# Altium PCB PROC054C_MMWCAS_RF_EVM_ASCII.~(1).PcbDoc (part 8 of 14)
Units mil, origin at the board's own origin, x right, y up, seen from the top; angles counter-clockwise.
Board outline 6299.21 x 5370.07 mil, 8 copper layers (L1 TOP, L2 GND, L3 SIGNAL 1, L4 GND, L5 SIGNAL 2, L6 SIGNAL 3, L7 GND, L8 BOTTOM), stack 53.5 mil thick; 775 components, 552 nets, 2648 pads, 7845 vias.
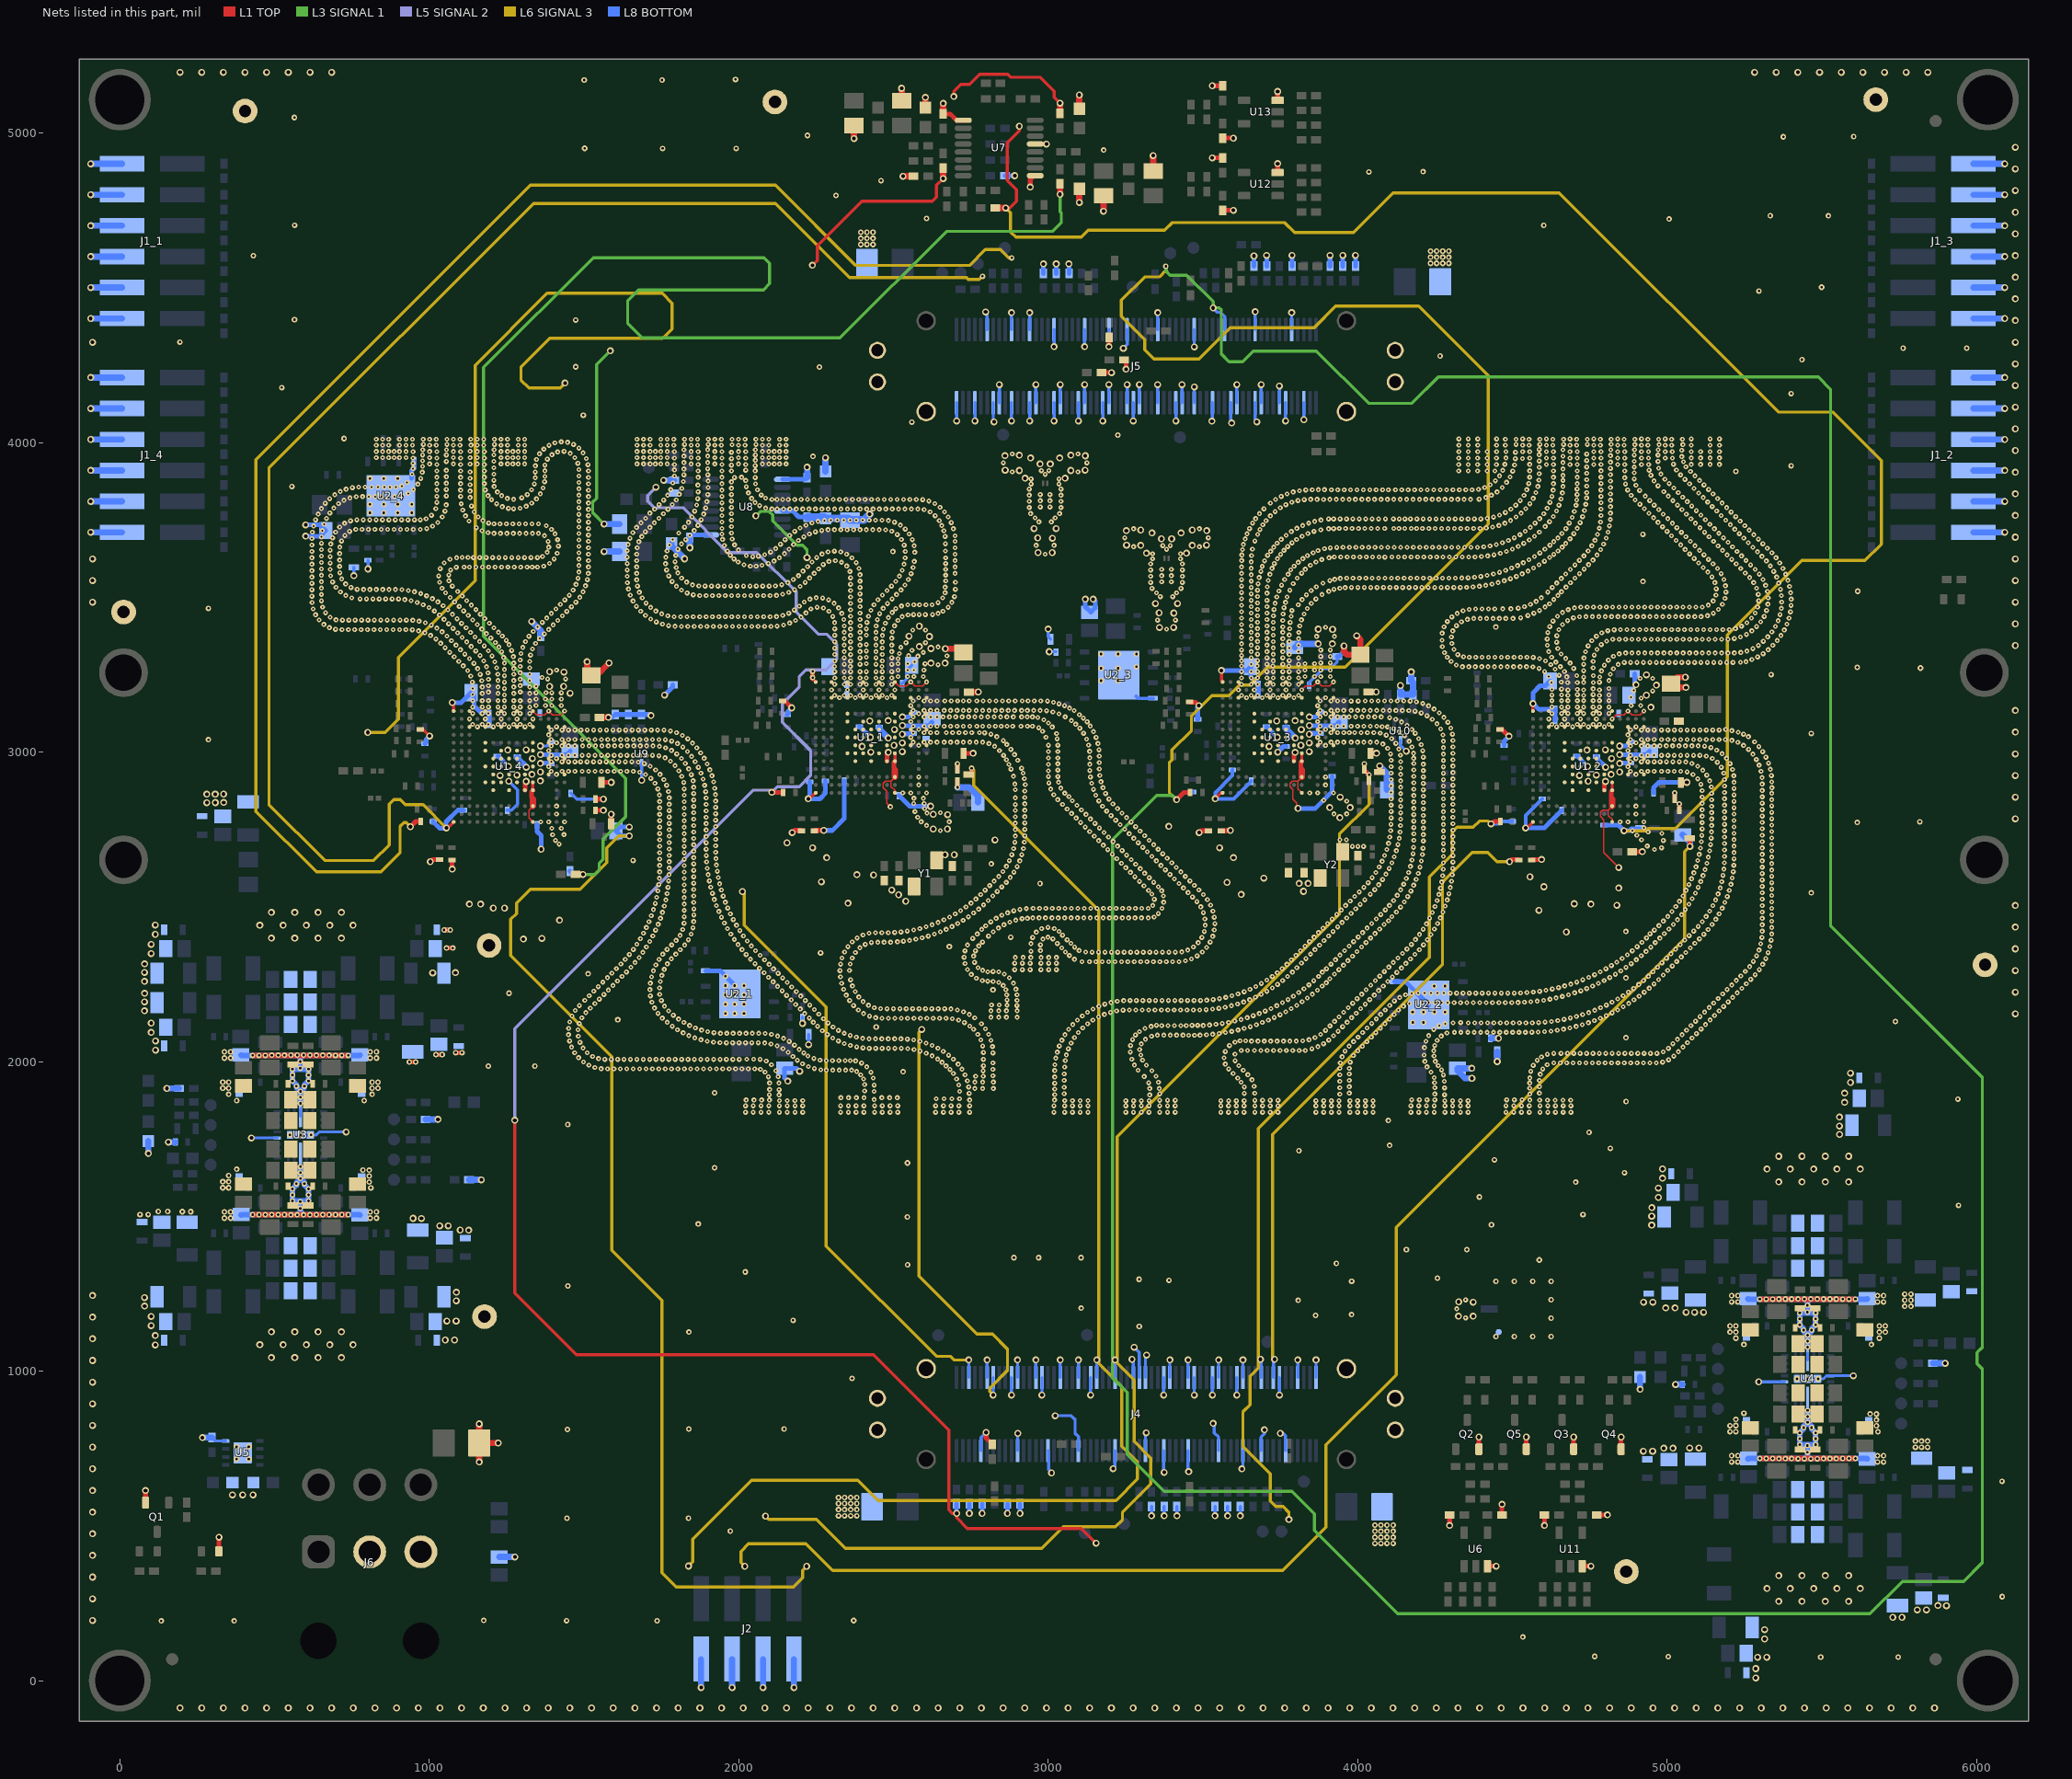
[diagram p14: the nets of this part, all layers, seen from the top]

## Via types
v1: diameter 13.77/15.74 (per signal layer), hole 5.9, L1 TOP to L2 GND, tented both sides, 5522 vias
v2: diameter 22.4, hole 12.2, L1 TOP to L8 BOTTOM, tented both sides, 1522 vias
v3: diameter 18, hole 8, L1 TOP to L8 BOTTOM, tented both sides, 727 vias
v4: diameter 18, hole 7.87, L1 TOP to L8 BOTTOM, tented top, 50 vias
v5: diameter 24, hole 12, L1 TOP to L8 BOTTOM, tented both sides, 13 vias
v6: diameter 19.68, hole 7.87, L1 TOP to L8 BOTTOM, tented top, 10 vias
v7: diameter 13.77/15.74 (per signal layer), hole 5.9, L1 TOP to L2 GND, tented top, 1 vias

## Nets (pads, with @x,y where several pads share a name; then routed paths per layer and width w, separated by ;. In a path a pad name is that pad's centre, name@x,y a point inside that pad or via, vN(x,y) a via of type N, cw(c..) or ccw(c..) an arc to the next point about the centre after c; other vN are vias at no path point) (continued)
GND: (continued)
  other v1: 4349.11,1172.28 4320.23,1201.17 4349.11,1230.06 2021.98,1836.34 2046.98,1836.34 2071.98,1836.34 2096.98,1836.34 2131.75,1836.34 2156.75,1836.34 2181.75,1836.34 2206.75,1836.34 2329.18,1836.34 2354.18,1836.34 2379.18,1836.34 2404.18,1836.34 2438.95,1836.34 2463.95,1836.34 2488.95,1836.34 2513.95,1836.34 2636.38,1836.34 2661.38,1836.34 2686.38,1836.34 2711.38,1836.34 2746.15,1836.34 3018.58,1836.34 3053.35,1836.34 3078.35,1836.34 3103.35,1836.34 3128.35,1836.34 3250.78,1836.34 3275.78,1836.34 3300.78,1836.34 3325.78,1836.34 3360.55,1836.34 3385.55,1836.34 3410.55,1836.34 3557.98,1836.34 3582.98,1836.34 3607.98,1836.34 3632.98,1836.34 3667.75,1836.34 3692.75,1836.34 3717.75,1836.34 3742.75,1836.34 3865.18,1836.34 3890.18,1836.34 3915.18,1836.34 3940.18,1836.34 3974.95,1836.34 3999.95,1836.34 4024.95,1836.34 4049.95,1836.34 4172.38,1836.34 4197.38,1836.34 4222.38,1836.34 4247.38,1836.34 4282.15,1836.34 4307.15,1836.34 4332.15,1836.34 4357.15,1836.34 4479.58,1836.34 4504.58,1836.34 4529.58,1836.34 4554.58,1836.34 4589.35,1836.34 4614.35,1836.34 4639.35,1836.34 4664.35,1836.34 4689.35,1836.34 2021.98,1857.01 2046.98,1857.01 2071.98,1857.01 2096.98,1857.01 2131.75,1857.01 2156.75,1857.01 2181.75,1857.01 2206.75,1857.01 2329.18,1857.01 2354.18,1857.01 2379.18,1857.01 2404.18,1857.01 2438.95,1857.01 2463.95,1857.01 2488.95,1857.01 2513.95,1857.01 2636.38,1857.01 2661.38,1857.01 2686.38,1857.01 2711.38,1857.01 2746.15,1857.01 3018.58,1857.01 3053.35,1857.01 3078.35,1857.01 3103.35,1857.01 3128.35,1857.01 3250.78,1857.01 3275.78,1857.01 3300.78,1857.01 3325.78,1857.01 3360.55,1857.01 3385.55,1857.01 3410.55,1857.01 3557.98,1857.01 3582.98,1857.01 3607.98,1857.01 3632.98,1857.01 3667.75,1857.01 3692.75,1857.01 3717.75,1857.01 3742.75,1857.01 3865.18,1857.01 3890.18,1857.01 3915.18,1857.01 3940.18,1857.01 3974.95,1857.01 3999.95,1857.01 4024.95,1857.01 4049.95,1857.01 4172.38,1857.01 4197.38,1857.01 4222.38,1857.01 4247.38,1857.01 4282.15,1857.01 4307.15,1857.01 4332.15,1857.01 4357.15,1857.01 4479.58,1857.01 4504.58,1857.01 4529.58,1857.01 4554.58,1857.01 4589.35,1857.01 4614.35,1857.01 4639.35,1857.01 4664.35,1857.01 4689.35,1857.01 2131.52,1874.05 2156.52,1874.05 2181.52,1874.05 2206.52,1874.05 3053.52,1874.05 3078.52,1874.05 3103.52,1874.05 3128.52,1874.05 3251.02,1873.55 3276.02,1873.55 3301.02,1873.55 3326.02,1873.55 3558.22,1873.55 3583.22,1873.55 3608.22,1873.55 3633.22,1873.55 3865.18,1873.55 3890.18,1873.55 3915.18,1873.55 3940.18,1873.55 3974.95,1873.55 3999.95,1873.55 4024.95,1873.55 4049.95,1873.55 4282.02,1873.55 4307.02,1873.55 4332.02,1873.55 4357.02,1873.55 3360.52,1875.05 3385.52,1875.05 3410.52,1875.05 3667.72,1875.05 3692.72,1875.05 3717.72,1875.05 3742.72,1875.05 4588.44,1875.48 4613.44,1875.48 4638.44,1875.48 4663.44,1875.48 4688.44,1875.48 2024.07,1875.88 2049.07,1875.88 2074.07,1875.88 2099.07,1875.88 2746,1876 3020.66,1875.94 4174.47,1876.36 4199.47,1876.36 4224.47,1876.36 4249.47,1876.36 4481.67,1876.48 4506.67,1876.48 4531.67,1876.48 4556.66,1876.12 2437.5,1877.63 2638.47,1879.93 2663.47,1879.93 2688.47,1879.93 2713.47,1879.94 2330.03,1883.3 2355.03,1883.3 2380.03,1883.3 2405.03,1883.3 2462.42,1883.3 2487.42,1883.3 2512.42,1883.3 2130.38,1892.3 3328.18,1892.34 2099,1893 3021.06,1893.43 4281,1893 3942.42,1895.05 4249.54,1895.11 4556.66,1895.14 3051.74,1896.3 3360.52,1895.72 2744.62,1897.27 3633.86,1897.29 3667.55,1897.85 3973.1,1898.3 4587.34,1898.3 2437.42,1903.97 2713.76,1903.82 2406.82,1905.33 2130.38,1908.97 2099.7,1910.17 3021.06,1911.1 2763.18,1913.14 2788.18,1913.14 2822.95,1913.14 3328.18,1913.01 3359.02,1913.17 4556,1914 4281,1915 3942.42,1915.72 4249.54,1915.78 3051.74,1916.97 2743.14,1917.89 3633.86,1917.96 3973.1,1918.97 4587.34,1918.97 3665.36,1920.35 2437.5,1923.97 2710.7,1924.26 2406.82,1926 3021.06,1929.77 2099.7,1930.84 2130.22,1931 3324.93,1931.36 4556,1931 4248.7,1932 2763.18,1933.81 2788.18,1933.81 2822.95,1933.81 3356.38,1933.67 3623.45,1933.7 3942.42,1936.39 4280.21,1936.44 2738.73,1938.08 3051.74,1939.64 3973.1,1939.64 4587.34,1939.64 3658.45,1941.4 2403.49,1943.7 2703.99,1943.81 2434.75,1946.58 3612.39,1946.91 4556.66,1947.48 4247.84,1948.23 3021.06,1950.44 2095.61,1950.94 2127.65,1951.51 3310.43,1951.87 2765.27,1952.87 2790.26,1952.68 3348.62,1952.83 2821.4,1954.43 2394.01,1957 2731.49,1957.44 3942.42,1957.06 4277.26,1956.9 3645.16,1957.52 4590.1,1959.41 3051.74,1960.31 3973.1,1960.31 2693.86,1961.83 3597.78,1961.52 2085,1966 2426.93,1965.71 4237.29,1966 2381,1968 4559.53,1968.76 2790,1970 3335.32,1970.36 2120.1,1970.75 3021.06,1971.11 3290.7,1971.97 3630.54,1972.14 2283.31,1972.59 2303.98,1972.59 2324.65,1972.59 2345.32,1972.59 2364.91,1972.59 4271.1,1973.15 2264.98,1973.68 2683.06,1974.35 2070,1975 2821.4,1975.1 2721.56,1975.57 3583.16,1976.14 4598.1,1976.05 1555.56,1977.19 1576.22,1976.72 1596.89,1976.72 1617.56,1976.72 1638.23,1976.72 1658.9,1976.72 1679.57,1976.72 1700.24,1976.72 1720.91,1976.72 1741.58,1976.72 1762.25,1976.72 1782.92,1976.72 1803.59,1976.72 1824.26,1976.72 1844.93,1976.72 1865.6,1976.72 1886.27,1976.72 1906.94,1976.72 1927.61,1976.72 1948.28,1976.72 1968.95,1976.72 1989.62,1976.72 2010.29,1976.72 2030.96,1976.72 2051.63,1976.72 2244.66,1977.48 3942.42,1977.73 3973.09,1977.72 1535.23,1980.91 3053.15,1982.35 2413.58,1983.1 4224.21,1982.8 2225.03,1983.96 2670.01,1986 2790.72,1986.61 3615.93,1986.75 4260.61,1987 1515.9,1988.23 3317.5,1988.18 4567.54,1987.81 3278.75,1988.83 2105.84,1989.84 3021.31,1989.95 4612.4,1989.95 2709.14,1992.09 3572.52,1991.76 2206.44,1992.98 2396.94,1995.36 2821.4,1995.77 3944.04,1995.88 4633.62,1995.66 4655.2,1995.66 4675.87,1995.66 4696.54,1995.66 4717.21,1995.66 4737.88,1995.66 4758.55,1995.66 4779.22,1995.66 4799.89,1995.66 4820.56,1995.66 4841.23,1995.66 4861.9,1995.66 4882.57,1995.66 4903.24,1995.66 4923.91,1995.66 4944.58,1995.66 4965.25,1995.67 2657.01,1998 3976.07,1998.17 4985.74,1998.41 1498.2,1998.91 4217.26,2000.65 4251.01,2001 2088.93,2001.72 2377.41,2002.12 2283.31,2003.26 2302.9,2003.27 2323.57,2003.27 2344.24,2003.27 2360.55,2003.27 3055.2,2003.15 3604.35,2002.75 2189.21,2004.4 4580.15,2004.19 2262.71,2004.98 3305.03,2004.67 5005.02,2005.86 1567.44,2007.4 1588.11,2007.4 1608.78,2007.4 1629.45,2007.4 1650.12,2007.4 1670.79,2007.4 1691.46,2007.4 1712.13,2007.4 1732.8,2007.4 1753.47,2007.4 1774.14,2007.4 1794.81,2007.4 1815.48,2007.4 1836.15,2007.4 1856.82,2007.4 1877.49,2007.4 1898.16,2007.4 1918.83,2007.4 1939.5,2007.4 1960.17,2007.4 1980.84,2007.4 2001.51,2007.4 2068.98,2007.15 2693.86,2007.49 2790.72,2007.28 2026,2008 2048,2008 2642.67,2008.19 3270.29,2007.69 1546.88,2009.59 2242.68,2010.08 3024.3,2011.41 3568.31,2012 1482.71,2012.6 4594.2,2015.25 2175.26,2016.4 3949.75,2015.75 1527.49,2016.73 2223.77,2018.43 2624.74,2018.47 4247.01,2018 5022.04,2017.6 3986.68,2019.68 2678.03,2020.79 3299.35,2021.16 4214.86,2021.05 3058.74,2021.71 3603.7,2023.85 4613.14,2023.51 4633.62,2026.34 4657.22,2026.34 4677.89,2026.34 4698.56,2026.34 4719.23,2026.34 4739.9,2026.34 4760.57,2026.34 4781.24,2026.34 4801.91,2026.34 4822.58,2026.34 4843.25,2026.34 4863.92,2026.34 4884.59,2026.34 4905.26,2026.34 4925.93,2026.34 4946.6,2026.34 4967.27,2026.44 2605.93,2027.04 1510.43,2028.42 2210,2028 2821.43,2027.98 1469.84,2028.77 2159.84,2030.18 2790.74,2029.66 3029.35,2030.52 3265.27,2031.1 4987.35,2031.35 5036.78,2032.09 2661.18,2032.75 3572.32,2032.65 2586.41,2033.83 3959.32,2034 4000.63,2034.94 4246.04,2034.83 3623.76,2035.72 3644.43,2035.72 3666.45,2035.72 3687.12,2035.72 3707.79,2035.72 3728.46,2035.72 3749.13,2035.72 3769.8,2035.72 3790.47,2035.72 3811.14,2035.73 3831,2036 2566.34,2038.79 3295.52,2038.86 2195.52,2039.52 3065.38,2041.29 3852,2041.37 2142.65,2041.64 2545.9,2041.86 2421.91,2043.07 2442.58,2043.03 2463.25,2043.03 2483.92,2043.03 2504.59,2043.03 2525.26,2043.02 2643.41,2043.31 5004.38,2043.07 1496.68,2043.85 2401.28,2044.32 4215.96,2045.32 1459.92,2046.91 2380.83,2047.33 5051.39,2046.7 3871.5,2048.24 2819.88,2048.59 2788.43,2050.2 3035.89,2050.12 3972.35,2050.04 4015.24,2049.55 2124,2050.57 2360.71,2052.06 2624.83,2052.37 3266.05,2051.76 3585.84,2051.78 4249.01,2052 2180.09,2053.28 2104.28,2056.76 3300.84,2057.21 2341.07,2058.49 3889.9,2057.65 5018.99,2057.68 2083.88,2060.11 2605.58,2059.9 3074.14,2060.01 1939.21,2061.03 1959.87,2060.72 1980.54,2060.72 2001.21,2060.72 2021.88,2060.72 2042.55,2060.72 2063.22,2060.72 5066.01,2061.32 1486.84,2062.02 1918.6,2062.72 3603.44,2062.62 4029.86,2064.17 2163.16,2065.14 3986.97,2064.66 4220.58,2065.47 1453.24,2066.47 1898.18,2065.88 2585.78,2065.83 3657.1,2066.4 3677.77,2066.4 3698.44,2066.4 3719.11,2066.4 3739.78,2066.4 3760.45,2066.4 3781.12,2066.4 3801.79,2066.4 2322.04,2066.57 3620,2067 3638,2067 3822.45,2066.97 2815.28,2068.74 3044.26,2069.02 3906.88,2069.44 4257,2068.71 2565.56,2070.12 2782.24,2069.92 1878.03,2070.5 3272.88,2071.27 3842.79,2070.66 3314.58,2072.33 5033.61,2072.3 2545.06,2072.75 2421.06,2073.77 2441.73,2073.71 2462.4,2073.71 2483.07,2073.71 2503.74,2073.71 2524.41,2073.71 2144.96,2074.93 2400.44,2075.29 2303.77,2076.25 5080.62,2075.93 1858.27,2076.55 3084.89,2077.66 3862.23,2077.69 2380.08,2078.81 4001.59,2079.28 4044.47,2078.78 1481.39,2081.96 3334.01,2082 2125.74,2082.54 3922.15,2083.36 4270.25,2082.71 1838.98,2084 2360.15,2084.29 4229.56,2084.08 3353.04,2085.35 3373.71,2085.35 3394.38,2085.35 3415.05,2085.35 3435.72,2085.35 3454.01,2085 3473,2085 3282.01,2086 3490.7,2085.69 1449.99,2086.88 2286.4,2087.44 3054.37,2087.05 3511.34,2086.72 5048.23,2086.92 2105.76,2087.84 2772.38,2088.09 2807.72,2087.98 3531.94,2088.43 3880.22,2087.86 1961.29,2091.4 1981.96,2091.4 2002.63,2091.4 2023.3,2091.4 2043.97,2091.4 2064.64,2091.4 2085.3,2090.77 3552.47,2090.83 5095.24,2090.55 1940.62,2091.67 2340.85,2091.7 4288.66,2092.25 1820.29,2092.81 1920.03,2093.45 4059.09,2093.4 3097.52,2094.03 3572.91,2093.91 4016.2,2093.89 4313.03,2094.66 4333.7,2094.66 4356.32,2094.66 4376.99,2094.66 4397.66,2094.66 4418.33,2094.66 4439,2094.66 4459.67,2094.66 4480.34,2094.66 4501.01,2094.66 4521.68,2094.66 4542.35,2094.66 4563.02,2094.7 4583.68,2095.29 1899.64,2096.88 3295.16,2096.61 4604.31,2096.61 3593.24,2097.66 3936.77,2097.98 4624.88,2098.64 2270.04,2100.07 2322.36,2100.94 3896.27,2100.89 4645.36,2101.38 1879.6,2101.92 3613.43,2102.08 5062.84,2101.53 1480.64,2102.62 1802.27,2102.94 2759.24,2104.04 3066.14,2104.04 4246.18,2103.76 4665.74,2104.84 5109.86,2105.17 2797.38,2105.88 3312.89,2107.23 3633.46,2107.18 1450.28,2107.55 4073.71,2108.02 1860.02,2108.56 3111.86,2108.91 4030.82,2108.51 4685.99,2109 2304.87,2111.95 3653.31,2112.93 3951.39,2112.6 1785.02,2114.33 2254.81,2114.05 3332.49,2113.8 4706.08,2113.86 2746.95,2114.8 3910.89,2115.49 3366.68,2116.03 3387.35,2116.03 3408.02,2116.03 3428.69,2116.03 3446,2116 4263.19,2115.51 5077.46,2116.15 1841.04,2116.74 3350.01,2117 3465.01,2117 3483,2117 3500.92,2116.84 3521.54,2118.27 3672.96,2119.34 4725.99,2119.42 3079.47,2119.84 3542.1,2120.43 5124.47,2119.78 2784.49,2122.04 3127.61,2122.3 1484.61,2122.9 3562.57,2123.31 4045.43,2123.12 4088.32,2122.63 4282.51,2122.85 2288.53,2124.61 4308.2,2125.34 4357.74,2125.34 4378.41,2125.34 4399.08,2125.34 4419.75,2125.34 4440.42,2125.34 4461.09,2125.34 4481.76,2125.34 4502.43,2125.34 4523.1,2125.34 4543.77,2125.34 4564.44,2125.4 1822.78,2126.42 2729.53,2125.93 3692.39,2126.4 4333,2126 4585.1,2126.08 4745.69,2125.67 1768.63,2126.93 2241,2127 3582.93,2126.89 3966,2127.21 1454.09,2127.86 4605.72,2127.52 3925.51,2130.11 4626.27,2129.71 3603.14,2131.19 5092.07,2130.76 4646.73,2132.65 4765.16,2132.6 2710.5,2134 3094.2,2134.34 3144.58,2134.1 3711.57,2134.1 5139.09,2134.4 3623.2,2136.18 4667.07,2136.35 4102.94,2137.25 1805.35,2137.53 4060.05,2137.74 2273.47,2138.77 2690.39,2138.77 2463.06,2140.14 2483.73,2140.14 2504.4,2140.14 2525.07,2140.14 2545.74,2140.14 2566.41,2140.14 2587.08,2140.14 2607.75,2140.14 2628.42,2140.14 2649.09,2140.14 2669.76,2140.14 4784.38,2140.21 1753.19,2140.67 2227.99,2140.87 2762.5,2141.46 4687.26,2140.78 1493.11,2141.74 2442.46,2141.83 3643.07,2141.88 3730.49,2142.43 3980.62,2141.83 2814.98,2143.54 2839.98,2143.54 2864.98,2143.54 2899.75,2143.54 3162.61,2144.21 3940.13,2144.73 5106.69,2145.38 4707.27,2145.96 1461.3,2147.23 2422.45,2146.98 3110.11,2147.53 3662.73,2148.26 4803.33,2148.48 5153.7,2149.01 1788.87,2150.01 3749.12,2151.39 2744.99,2152.46 4074.66,2152.35 4117.55,2151.86 4727.08,2151.86 2258.85,2153.39 3181.53,2152.54 2213.37,2155.49 2403.58,2155.44 3682.15,2155.33 1739.12,2155.81 3995.23,2156.44 4821.97,2157.4 1505.68,2158.15 4746.66,2158.49 3127.08,2159.33 3201.16,2159 3954.74,2159.34 5121.31,2160 2726.17,2161 3767.44,2160.96 3701.32,2163.07 1773.44,2163.76 2814.98,2164.21 2839.98,2164.21 2864.98,2164.21 2899.75,2164.21 3221.33,2163.53 5168.32,2163.63 1471.72,2165.09 3241.84,2166.1 4132.17,2166.48 4765.98,2165.83 2386.42,2166.96 2706.38,2166.95 3262.5,2166.72 3283.17,2166.72 3303.84,2166.72 3324.51,2166.72 3345.18,2166.72 3365.85,2166.72 3386.52,2166.72 3407.19,2166.72 3427.86,2166.72 3448.53,2166.72 3469.2,2166.72 3489.87,2166.79 4089.28,2166.97 4840.3,2166.96 2244.24,2168 3510.52,2167.62 3531.12,2169.41 2198.76,2170.1 2685.96,2170.19 3144.99,2169.66 2458.6,2170.91 2479.27,2170.82 2499.94,2170.82 2520.61,2170.82 2541.28,2170.82 2561.95,2170.82 2582.62,2170.82 2603.29,2170.82 2623.96,2170.82 2644.63,2170.82 2665.3,2170.82 3720.2,2171.48 3785.44,2171.13 4009.85,2171.06 3551.6,2172.15 1520.29,2172.78 1727.75,2173.07 2438.19,2174.18 3969.36,2173.96 4785.02,2173.87 5135.92,2174.61 3571.94,2175.83 4858.28,2177.16 3163.7,2178.44 5182.94,2178.25 1759.85,2179.34 4148.56,2179.08 3592.09,2180.45 1485.03,2180.9 2371.41,2181.17 2899,2181 3738.78,2180.54 2419.04,2181.95 2867.06,2182.35 3803.08,2181.89 4103.9,2181.59 2229.62,2182.62 2817.07,2183.08 2842.07,2183.08 4803.75,2182.61 2184.14,2184.72 3183.09,2185.61 3612,2186 4024.46,2185.68 1534.9,2187.39 4167.52,2187.3 4875.89,2187.97 3983.97,2188.57 5150.54,2189.23 3757.03,2190.24 3203.01,2191.11 4187.92,2190.65 4208.59,2190.72 4229.26,2190.72 4249.93,2190.72 4270.6,2190.72 4291.27,2190.72 4311.94,2190.72 4332.61,2190.72 4353.28,2190.72 4373.95,2190.72 4394.62,2190.72 4415.29,2190.72 4435.96,2190.72 4456.63,2190.72 4477.3,2190.72 4497.97,2190.72 4518.63,2190.9 1719.48,2192.01 3631.63,2192.47 4539.29,2191.72 4822.15,2192.03 3820.36,2193.24 4559.9,2193.21 5197.55,2192.86 2402.13,2193.84 3223.33,2194.91 4580.46,2195.36 4118.94,2195.76 2215.01,2197.23 2358.42,2197.25 3243.9,2196.99 3264.56,2197.4 3285.23,2197.4 3305.9,2197.4 3326.57,2197.4 3347.24,2197.4 3367.91,2197.4 3388.58,2197.4 3409.25,2197.4 3429.92,2197.4 3450.59,2197.4 3471.26,2197.4 1502.33,2198.2 1750.1,2197.56 2899.01,2198 3491.93,2197.51 4600.94,2198.18 2169.53,2199.33 2867,2199 3512.58,2198.51 4893.12,2199.39 3650.95,2199.83 4039.08,2200.29 3533.15,2200.53 3774.94,2200.57 1549.52,2202.01 4621.31,2201.66 4840.2,2202.11 3998.59,2203.19 3553.59,2203.57 5165.15,2203.84 3837.26,2205.15 4641.57,2205.8 4136.1,2207.28 5212.17,2207.48 3573.86,2207.62 3669.9,2208.08 2388.01,2208.93 4661.67,2210.59 4909.94,2211.41 1714.54,2212.09 2200.39,2211.85 3792.47,2211.52 1516.94,2212.81 3593.9,2212.68 4857.86,2212.86 2154.91,2213.95 2347.49,2214.79 4053.69,2214.91 2866,2216 2899.01,2216 4155.05,2215.54 4681.62,2216.02 1564.14,2216.62 3688.45,2217.21 1744.74,2217.53 3853.74,2217.61 4013.21,2217.81 5179.77,2218.46 3613.67,2218.73 4175.17,2220.27 4195.81,2221.4 4216.48,2221.4 4237.15,2221.4 4257.82,2221.4 4278.49,2221.4 4299.16,2221.4 4319.83,2221.4 4340.5,2221.4 4361.17,2221.4 4381.84,2221.4 4402.51,2221.4 4423.18,2221.4 4443.85,2221.4 4464.52,2221.4 4485.19,2221.4 4505.86,2221.4 4526.53,2221.83 4701.37,2222.1 5226.78,2222.09 3809.6,2223.08 4547.17,2222.96 4875.11,2224.24 4926.33,2224 4567.76,2224.79 2185.77,2226.47 2376.36,2226.01 3633.11,2225.75 1531.56,2227.43 3706.55,2227.17 4588.27,2227.32 2140.29,2228.57 4720.92,2228.82 4068.31,2229.53 1578.75,2231.24 3869.81,2230.61 4608.69,2230.55 2863,2232 4027.82,2232.42 1713.09,2232.7 5194.39,2233.08 2338.8,2233.55 2895.57,2234.14 3652.18,2233.72 4628.98,2234.46 3826.33,2235.23 4740.24,2236.16 4891.93,2236.25 4942.28,2237.15 5241.4,2236.71 1743.92,2238.18 3724.18,2237.97 4649.13,2239.07 2171.16,2241.08 1546.18,2242.04 2125.68,2243.18 3670.83,2242.64 3885.44,2244.15 4082.93,2244.14 4669.12,2244.35 4759.31,2244.13 2367.4,2244.63 1593.37,2245.85 2854.56,2246.1 4042.44,2247.04 3842.61,2247.96 5209,2247.69 4908.31,2248.86 3741.29,2249.57 4688.91,2250.32 4957.75,2250.86 5256.02,2251.33 3689.01,2252.47 1714.46,2253.33 2332.48,2253.22 2887.81,2253.3 4778.12,2252.71 3899,2255 2156.54,2255.7 2840.01,2256 1560.79,2256.66 4708.49,2256.95 2111.06,2257.8 1746.3,2258.71 2822,2259 4097.54,2258.76 1607.99,2260.47 2804.33,2259.66 3858.45,2261.24 2787.32,2261.62 3757.84,2261.95 4057.05,2261.65 4796.64,2261.89 4924.21,2262.07 5223.62,2262.31 3706.68,2263.19 2361.34,2264.4 4727.83,2264.24 4972.75,2265.09 5270.63,2265.94 3910.37,2267.74 2768.04,2269.07 2141.93,2270.31 1575.41,2271.27 2874.56,2270.74 2096.45,2272.41 4746.91,2272.19 4814.85,2271.67 4112.16,2273.37 1718.14,2273.67 2328.62,2273.53 1622.6,2275.08 3723.8,2274.78 3773.8,2275.09 3873.81,2275.07 4071.67,2276.27 4939.61,2275.85 5238.23,2276.92 1751.43,2278.74 4987.38,2279.69 4765.71,2280.77 5284.96,2280.84 2751.54,2281.52 3924.99,2282.36 4832.74,2282.03 2857.86,2282.92 2127.31,2284.93 1590.03,2285.89 2081.83,2287.03 3740.32,2287.2 4126.77,2287.99 3789.14,2288.94 3886,2289 1637.22,2289.7 2804.33,2290.34 2840,2290 4784.21,2290 4954.5,2290.19 2822,2291 4086.29,2290.89 5252.85,2291.54 1724.08,2293.47 4850.28,2292.96 2327.28,2294.16 5001.99,2294.3 2357.96,2294.69 2788.45,2295.1 2891.78,2297.14 2916.78,2297.14 2941.78,2297.14 2976.55,2297.14 3001.55,2297.14 3026.55,2297.14 3939.6,2296.97 5297.88,2296.97 1759.21,2297.89 2739.11,2297.67 2112.69,2299.55 3756.2,2300.43 3899.32,2300.07 4802.38,2299.84 1604.64,2300.5 2067.22,2301.64 2773.23,2303.22 3803.87,2303.44 4141.39,2302.61 4867.46,2304.46 1651.48,2304.66 4100.9,2305.5 4969.12,2304.81 5266.77,2306.81 5016.61,2308.92 4820.21,2310.3 1732.2,2312.47 3954.22,2311.59 2098.08,2314.16 3771.41,2314.43 5309.17,2314.29 1619.23,2315.15 2328.87,2314.77 2360.16,2315.24 3913.94,2314.69 1769.5,2315.81 2052.6,2316.26 2731.15,2316.74 4156,2317.22 4884.25,2316.5 2891.78,2317.81 2916.78,2317.81 2941.78,2317.81 2976.55,2317.81 3001.55,2317.81 3026.55,2317.81 3818.49,2318.06 4983.73,2319.42 1665.08,2320.22 4115.52,2320.12 2762.08,2320.62 4837.67,2321.36 3109,2323 3133.47,2322.66 3154.14,2322.66 3174.81,2322.66 3195.48,2322.66 3216.15,2322.66 3236.82,2322.66 3257.49,2322.66 3278.16,2322.66 3298.83,2322.66 3319.5,2322.66 3340.17,2322.66 3360.84,2322.66 3381.51,2322.66 3402.18,2322.66 3422.85,2322.83 5031.22,2323.53 5278.89,2323.56 3443.32,2325.67 3968.83,2326.2 2083.46,2328.78 3786.06,2329.01 3928.56,2329.31 4900.65,2329.08 1633.29,2330.3 1742.42,2330.44 2038.04,2330.94 3085.17,2330.57 1782.12,2332.19 3463.02,2331.92 4170.62,2331.84 3833.1,2332.67 4854.75,2333 5318.74,2332.61 4998.35,2334.04 2333.76,2334.85 2366.67,2334.86 4130.13,2334.73 1677.99,2336.37 2728.4,2337.23 2893.87,2336.68 2918.87,2336.68 2943.87,2336.68 2976.72,2336.68 3001.72,2336.68 3026.72,2336.68 5045.84,2338.15 2759.22,2341.1 3481.39,2341.4 3983.45,2340.82 4916.64,2342.19 5289.03,2341.57 2068.85,2343.39 3068.53,2342.83 3800.68,2343.63 3943.17,2343.92 4871.42,2345.22 1646.63,2346.09 2024,2346.1 4185.23,2346.46 1754.58,2347.15 1796.53,2347.01 3847.72,2347.29 4144.75,2349.35 5012.96,2348.65 5326.48,2351.78 1690.18,2353.06 2377.2,2352.65 3142.09,2353.34 3162.76,2353.34 3183.43,2353.34 3204.1,2353.34 3224.77,2353.34 3245.44,2353.34 3266.11,2353.34 3286.78,2353.34 3307.45,2353.34 3328.12,2353.34 3348.79,2353.34 3369.46,2353.34 3390.13,2353.34 3410.8,2353.34 5060.46,2352.77 2341.84,2353.88 3055.55,2354.15 3121,2354 3497.89,2353.85 3431.43,2354.59 3998.07,2355.44 2944.28,2356.3 4932.19,2355.8 2054.45,2358.22 2731.07,2357.73 2765,2358 3815.29,2358.24 4887.67,2358 2974.96,2359.02 3100,2359 3957.79,2358.54 3451.31,2360.27 5297.07,2360.62 1659.22,2362.49 1768.54,2362.4 1811.14,2361.62 2010.58,2361.82 3862.33,2361.91 4199.38,2361.53 5027.58,2363.27 4159.37,2363.97 3044.17,2367.2 5075.07,2367.38 2391.3,2367.76 3512.06,2368.9 1701.63,2370.27 3085.75,2369.85 3469.39,2370.27 4012.68,2370.05 4947.29,2369.92 2352.88,2371.35 4903.48,2371.32 5332.33,2371.6 3829.91,2372.86 3972.4,2373.15 2040.68,2373.64 2776,2374 1783.16,2377.02 1825.37,2376.62 2738.96,2376.83 2975.03,2377.04 3876.95,2376.52 4212.78,2377.27 1997.8,2378.07 5042.2,2377.89 1671.02,2379.45 2408.78,2378.79 4173.69,2378.86 5302.9,2380.45 2944.49,2381.09 3029.55,2381.81 3073.5,2382.1 5089.69,2382 3484.77,2384.08 4961.98,2384.46 2428.56,2384.79 4027.3,2384.67 4918.82,2385.17 2449.21,2385.77 2469.88,2385.77 2490.55,2385.77 2787.85,2386.16 3523.49,2386.13 2366.6,2386.8 2513,2387 3844.52,2387.48 1712.31,2387.97 3987.02,2387.77 2532,2389 2027.6,2389.64 3891.56,2391.14 1797.74,2391.66 2552.05,2391.74 5336.22,2391.9 5056.81,2392.5 1837.22,2393.55 3060.99,2393.75 4187.23,2394.48 4225.41,2393.63 1985.69,2394.82 2572.38,2395.48 2982.82,2396.19 3014.94,2396.43 1682.03,2396.95 5104.3,2396.61 2756.27,2397.96 4041.91,2399.28 4976.59,2399.08 2382.88,2399.54 2592.53,2400.11 4933.68,2399.54 2949.58,2401.13 3496.66,2400.99 5306.44,2400.81 2999.15,2401.95 3859.14,2402.09 4001.63,2402.38 2807.19,2405.5 3531.84,2405.03 1722.22,2406.11 2015.21,2406.19 2612.44,2405.63 3906.18,2405.75 5071.43,2407.12 1810.22,2408.14 3046.38,2408.37 2401.3,2408.93 4199.94,2410.78 4237.23,2410.59 5118.83,2411.32 1846.16,2412.19 1974.27,2412.05 2632.1,2412.03 5338.13,2412.48 2770.88,2412.57 4945,2413 4056.53,2413.9 4991.21,2413.7 1692.2,2414.94 2421.16,2414.64 2441.75,2416.45 2462.42,2416.45 2483.09,2416.48 2503.75,2417.23 3873.75,2416.71 4016.25,2417 2961.64,2418.38 2524.35,2418.96 2651.46,2419.28 2822.53,2419.35 3504.44,2420.14 3920.8,2420.37 3035.15,2420.95 5307.66,2421.45 2544.84,2421.66 5086.04,2421.73 2003.54,2423.25 1731.32,2424.67 2565.19,2425.32 3536.89,2425.08 4958.89,2424.76 1818.87,2426.91 2670.47,2427.38 2785.5,2427.19 5132.61,2426.73 4211.78,2427.72 4248.21,2428.1 5005.82,2428.31 4071.14,2428.51 1963.55,2429.72 2585.33,2429.94 2978.9,2429.76 3019.45,2429.62 3888.37,2431.32 1851.95,2432.03 2839.21,2431.56 4030.87,2431.62 1701.52,2433.39 5338.34,2433.15 2999.19,2433.7 2605.24,2435.5 3935.41,2434.99 2689.11,2436.32 5100.43,2436.57 2798.19,2438.97 4973.51,2439.37 1992.62,2440.8 3507.72,2440.55 2624.86,2442 2857.05,2442 5307.66,2442.12 4085.76,2443.13 5020.17,2443.19 5145.47,2442.91 1739.6,2443.61 4222.72,2445.26 2707.34,2446.07 3538.49,2445.68 3902.99,2445.94 4045.48,2446.23 4258.34,2446.12 1823.3,2447.1 1953.55,2447.81 2644.15,2449.42 3950.03,2449.6 2875.87,2450.56 1709.97,2452.25 2814.43,2451.75 5113.9,2452.25 1854.44,2452.55 4988.11,2454 5338.34,2453.82 4100,2455 2725.12,2456.61 2895.46,2457.15 2663.07,2457.75 1982.45,2458.8 5033.85,2458.69 5157.37,2459.81 3506.59,2461.19 3917.6,2460.56 4060.1,2460.85 2915.62,2461.71 1747.05,2462.89 2831.75,2463.04 2933,2463 4232.74,2463.34 5307.66,2462.79 3964.64,2464.22 2950.01,2464.66 2970.68,2464.66 2991.35,2464.66 3012.02,2464.66 3032.69,2464.66 3053.36,2464.66 3074.03,2464.66 3094.7,2464.66 3115.37,2464.66 3136.04,2464.66 3156.71,2464.66 3177.38,2464.66 3198.05,2464.66 3218.72,2464.66 3239.39,2464.66 3260.06,2464.66 3280.73,2464.66 3301.4,2464.66 3323.28,2464.66 4267.58,2464.61 1944.29,2466.29 3536.84,2466.29 2681.58,2466.96 3342,2467 1823.86,2467.77 2742.41,2467.93 4111.02,2468.39 5002.25,2469.08 5126.34,2468.76 1717.54,2471.49 2850,2472.74 1855,2474 5338.34,2474.49 3932.22,2475.17 4074.71,2475.46 5046.83,2474.77 1973.07,2477.22 2699.63,2477.03 5168.26,2477.38 3355.84,2478.15 3979.26,2478.83 2759.19,2480 2869.03,2480.79 3501.61,2481.25 1753.65,2482.48 4241.79,2481.93 4125.19,2483.44 5307.66,2483.46 4275.92,2483.52 1935.79,2485.13 5015.66,2484.81 3532.19,2486.43 5137.7,2486.03 2888.71,2487.12 1823.86,2488.44 2717.18,2487.94 3946.83,2489.79 4089.33,2490.08 1724.19,2491.06 5059.09,2491.42 2908.87,2491.67 1855,2493 2775.42,2492.8 3993.87,2493.45 2929.36,2494.42 2951.22,2495.34 2971.89,2495.34 2992.56,2495.34 3013.23,2495.34 3033.9,2495.34 3054.57,2495.34 3075.24,2495.34 3095.91,2495.34 3116.58,2495.34 3137.25,2495.34 3157.92,2495.34 3178.59,2495.34 3199.26,2495.34 3219.93,2495.34 3240.6,2495.34 3261.27,2495.34 3281.94,2495.34 3302.61,2495.34 3323.28,2495.34 3367.78,2495.02 5338.34,2495.16 1964.49,2496.02 5178.12,2495.55 4138.44,2499.3 2734.2,2499.67 3492.97,2500.03 4249.87,2500.95 5028.31,2501.16 1759.39,2502.33 4283.33,2502.82 1928.05,2504.3 3337.93,2504.44 3961.45,2504.41 5147.94,2503.98 5307.66,2504.13 4103.02,2504.66 2791.07,2506.31 3524.65,2505.67 4008.49,2508.07 1823.86,2509.11 5070.6,2508.58 1729.93,2510.92 2750.64,2512.2 5186.9,2514.26 1854.54,2514.56 1956.73,2515.18 3373.44,2514.9 4150.72,2515.93 5338.34,2515.83 3480.98,2516.86 5040.17,2518.08 3976.06,2519.02 2806.1,2520.49 4256.94,2520.38 4116.16,2520.62 1764.25,2522.42 4289.8,2522.45 4023.1,2522.68 5157.03,2522.55 1921.08,2523.76 3342.98,2524.48 3514.37,2523.61 2766.48,2525.48 5307.66,2524.8 5081.34,2526.24 1823.86,2529.78 1734.73,2531.02 3466.57,2531.68 4161.98,2533.26 5194.58,2533.45 3990.68,2533.64 1854.54,2535.23 1949.79,2534.65 2820.73,2535.1 3372.17,2535.53 5051.22,2535.55 4128.23,2537.4 5338.34,2536.5 2781.67,2539.5 3501.58,2539.85 4262.99,2540.14 3335,2541 4041.07,2540.65 4295.31,2542.37 5164.91,2541.66 1768.24,2542.7 1914.92,2543.49 5091.3,2544.36 5307.66,2545.47 3451.95,2546.3 4005.29,2548.25 1823.86,2550.45 2835.34,2549.71 1738.58,2551.33 4172.18,2551.24 3367,2552 3324.13,2553.19 5201.13,2553.05 1943.7,2554.4 2796.33,2554.08 5061.44,2553.52 3487.07,2554.56 4139.17,2554.93 1854.54,2555.9 4055.23,2555.71 5338.34,2557.17 4268,2560.19 3437.33,2560.92 5171.56,2561.23 1771.33,2563.14 1909.55,2563.45 4019.91,2562.87 4299.85,2562.54 5100.44,2562.9 2849.96,2564.33 3355.84,2564.86 5307.66,2566.14 3309.51,2567.81 2810.94,2568.69 3472.45,2569.18 4181.3,2569.79 1823.86,2571.12 1741.49,2571.8 4068.43,2571.62 5070.79,2571.95 4148.94,2573.15 5206.54,2573 1938.46,2574.39 3422.72,2575.53 1854.54,2576.57 4033.98,2578.01 5338.34,2577.84 2864.39,2579.13 3341.23,2579.48 4271.96,2580.48 5176.95,2581.18 3294.9,2582.43 5108.75,2581.82 2825.56,2583.31 4303.41,2582.9 1773.53,2583.69 1904.99,2583.61 3457.84,2583.79 5307.66,2586.81 4080.62,2588.31 4189.28,2588.86 3408.1,2590.15 5079.26,2590.81 1743.44,2592.37 1823.86,2591.79 4157.49,2591.97 5210.77,2593.23 3326.61,2594.09 4046.99,2594.07 1934.08,2594.6 2877.6,2595.03 1854.54,2597.24 3280.28,2597.04 2840.08,2598.01 3443.22,2598.41 5338.34,2598.51 4274.86,2600.95 5116.23,2601.09 5181.06,2601.44 4305.98,2603.41 1774.83,2604.32 1901.25,2603.94 3393.49,2604.76 4091.76,2605.72 5307.66,2607.48 4196.12,2608.37 3312,2608.71 5086.83,2610.04 4058.88,2610.98 4164.79,2611.31 1823.86,2612.46 2889.34,2612.04 3265.67,2611.66 1744.42,2613.02 3428.6,2613.03 2853.37,2613.84 5213.82,2613.68 1930.57,2614.97 1854.54,2617.91 3378.87,2619.38 5338.34,2619.18 5122.84,2620.68 4276.68,2621.54 5183.88,2621.92 3297.38,2623.33 1898.33,2624.4 4101.8,2623.79 4307.55,2624.02 1775.23,2624.99 3251.05,2626.28 3413.99,2627.64 4201.77,2628.25 5307.66,2628.15 4069.59,2628.66 2899.5,2630.04 5093.49,2629.61 2864.96,2630.96 4170.81,2631.08 1823.86,2633.13 1744.55,2633.69 3364.26,2633.99 5215.68,2634.26 1927.94,2635.47 3282.77,2637.94 1854.54,2638.58 5338.34,2639.85 3236.44,2640.89 5128.58,2640.53 3399.37,2642.26 4110.7,2642.44 4277.43,2642.19 5185.38,2642.53 1896.24,2644.97 4308.13,2644.68 1775.23,2645.66 4079.07,2647.03 4206.23,2648.43 2874.72,2649.18 2908.02,2648.87 3349.64,2648.61 5099.21,2649.47 5307.66,2648.82 4175.51,2651.21 3268.15,2652.56 1744.55,2654.36 1823.86,2653.8 5216.34,2654.92 1926.19,2656.06 3221.82,2655.51 3384.76,2656.87 1854.54,2659.25 5133.44,2660.62 5338.34,2660.52 4118.44,2661.61 3335.02,2663.23 4277.45,2662.86 5185.66,2663.2 4308.13,2665.35 1775.23,2666.33 1894.98,2665.6 4087.28,2666 3253.54,2667.18 2882.55,2668.31 2914.82,2668.39 4209.47,2668.84 5307.66,2669.49 3207.21,2670.13 5103.99,2669.58 3370.14,2671.49 4178.89,2671.6 1823.86,2674.47 1744.55,2675.03 5216.34,2675.59 1925.33,2676.72 3320.41,2677.84 1854.54,2679.92 4124.97,2681.22 5137.4,2680.91 5338.34,2681.19 3238.92,2681.79 4277.45,2683.53 5185.66,2683.87 3192.59,2684.74 4094.19,2685.48 1894.55,2686.26 3355.52,2686.11 4308.13,2686.02 4959.4,2685.51 1775.23,2687 2888.36,2688.15 2919.84,2688.44 4211.49,2689.42 5107.81,2689.9 5307.66,2690.16 4982.28,2690.68 3305.79,2692.46 4180.92,2692.17 1823.86,2695.14 3982.88,2695.12 4000.88,2695.12 4019.22,2695.12 1744.55,2695.7 3224.31,2696.41 5216.34,2696.26 1925.23,2697.39 4936,2696.5 3177.98,2699.36 1854.54,2700.59 3340.91,2700.72 4130.28,2701.2 5140.47,2701.35 5338.34,2701.86 1419.35,2702.75 4277.45,2704.2 4099.75,2705.39 5185.66,2704.54 1894.55,2706.93 3291.18,2707.07 4308.13,2706.69 1775.23,2707.67 2892.1,2708.48 2923.05,2708.86 5110.66,2710.37 3209.69,2711.03 5307.66,2710.83 4212.28,2712.83 3163.36,2713.98 4988.28,2714.4 1407.67,2714.67 3326.29,2715.34 4181.6,2714.95 1744.55,2716.37 1823.86,2715.81 3942.87,2716.58 3963.92,2716.75 4917.07,2716.75 5216.34,2716.93 1925.23,2718.06 1854.54,2721.26 4134.35,2721.46 3276.56,2721.69 5142.63,2721.91 5338.34,2722.53 4277.45,2724.87 5185.66,2725.21 3195.08,2725.65 4103.94,2725.63 4308.13,2727.36 1775.23,2728.34 1894.55,2727.6 2893.73,2729.08 2924.43,2729.49 3148.75,2728.6 3311.68,2729.95 4902.46,2731.36 5112.55,2730.95 5307.66,2731.5 1398.45,2733.16 4212.28,2733.5 1823.86,2736.48 3261.94,2736.31 4181.6,2735.62 1744.55,2737.04 4983.12,2737.28 5216.34,2737.6 1925.23,2738.73 3180.46,2740.26 1854.54,2741.93 4137.16,2741.94 4939,2742 3134.13,2743.21 5143.88,2742.54 5338.34,2743.2 3297.06,2744.57 2651.3,2746.31 4106.75,2746.11 4277.45,2745.54 4887.84,2745.98 5185.66,2745.88 1894.55,2748.27 4308.13,2748.03 1775.23,2749.01 2893.8,2749.75 2924.48,2750.16 3247.33,2750.92 5113.46,2751.6 5307.66,2752.17 1396.09,2753.7 1426.77,2753.7 4212.28,2754.17 3165.85,2754.88 4925.5,2755.5 4181.6,2756.29 1823.86,2757.15 1744.55,2757.71 3119.52,2757.83 5216.34,2758.27 1925.23,2759.4 3282.45,2759.18 1854.54,2762.6 2606.86,2763.1 4138.69,2762.55 5144.23,2763.21 5338.34,2763.87 3232.71,2765.54 4277.45,2766.21 4108.15,2766.73 5185.66,2766.55 1894.55,2768.94 3151.23,2769.5 4308.13,2768.7 1775.23,2769.68 2893.8,2770.42 2924.48,2770.83 3104.9,2772.45 5113.55,2772.27 5307.66,2772.84 1360.25,2774.37 1385.84,2774.37 1437.03,2774.36 3267.83,2773.8 4848.25,2774.37 4873.84,2774.37 4925.03,2774.36 2589.8,2774.85 2680.18,2775.2 4212.28,2774.84 4181.6,2776.96 1744.55,2778.38 1823.86,2777.82 5216.34,2778.94 1925.23,2780.07 3218.1,2780.15 1854.54,2783.27 4139.01,2783.22 3136.62,2784.11 5144.23,2783.88 5338.34,2784.54 3090.29,2787.06 4108.33,2787.4 4277.45,2786.88 5185.66,2787.22 3253.21,2788.42 2578.1,2789.31 4308.13,2789.37 1775.23,2790.35 1894.55,2789.61 2893.8,2791.09 2924.48,2791.5 5113.55,2792.94 5307.66,2793.51 3203.48,2794.77 4212.28,2795.51 1823.86,2798.49 4181.6,2797.63 1744.55,2799.05 3122,2798.73 1411.43,2799.96 3923.66,2800.47 3964.51,2800.48 4899.43,2799.96 5216.34,2799.61 1925.23,2800.74 3075.67,2801.68 2608.4,2803.25 3238.6,2803.03 1854.54,2803.94 2651.3,2804.09 4139.01,2803.89 5144.23,2804.55 5338.34,2805.21 2569.16,2807.95 4108.33,2808.07 4277.45,2807.55 5185.66,2807.89 3188.93,2809.46 1894.55,2810.28 4308.13,2810.04 1775.23,2811.02 2893.8,2811.76 2924.48,2812.17 3107.39,2813.35 5113.55,2813.61 5307.66,2814.18 3061.06,2816.3 4212.28,2816.18 2600.45,2817.46 3223.98,2817.65 4181.6,2818.3 1823.86,2819.16 1744.55,2819.72 5216.34,2820.28 1925.23,2821.41 1854.54,2824.61 3175.58,2825.23 4139.01,2824.56 5144.23,2825.22 1411.43,2825.55 4899.43,2825.55 5338.34,2825.88 3092.77,2827.96 4277.45,2828.22 4108.33,2828.74 5185.66,2828.56 2893.8,2830.43 1894.55,2830.95 3046.44,2830.91 4308.13,2830.71 1775.23,2831.69 3209.5,2832.4 2924.48,2832.84 2565.15,2834.01 2599,2834.01 5113.55,2834.28 5307.66,2834.85 4212.28,2836.85 4181.6,2838.97 1744.55,2840.39 1823.86,2839.83 3964.52,2841.33 5216.34,2840.95 1925.23,2842.08 3163.92,2842.3 3078.16,2842.58 1854.54,2845.28 3890.5,2844.5 4139.01,2845.23 3031.07,2846.3 5144.23,2845.89 5338.34,2846.55 3196.54,2848.5 4108.33,2849.41 4277.45,2848.89 5185.66,2849.23 2566.09,2850.65 2596.77,2850.65 4308.13,2851.38 1775.16,2852.36 1894.49,2851.62 2894,2852.33 2924.48,2853.51 5113.55,2854.95 3067,2856 5307.66,2855.52 4212.28,2857.52 3154.08,2860.48 4181.6,2859.64 1743.66,2861.04 1823.86,2860.5 3018.1,2862.39 5216.34,2861.62 1924.71,2862.74 1854.54,2865.95 3185.64,2866.06 4139.01,2865.9 3053.52,2867.22 5144.23,2866.56 5338.34,2867.22 2530.25,2868.37 2555.84,2868.37 2607.02,2868.37 3845.25,2868.37 3870.84,2868.37 3922.07,2868.37 4108.33,2870.08 4277.45,2869.56 5185.66,2869.9 1893.08,2872.24 4308.13,2872.05 1772.73,2872.89 2924.48,2874.18 5113.48,2875.62 5307.66,2876.19 2894,2878.33 4212.28,2878.19 3146.16,2879.57 4181.6,2880.31 1738.52,2881.06 1823.86,2881.17 3008.47,2880.68 5216.34,2882.29 1922.58,2883.3 3041.02,2883.68 3176.94,2884.81 5339,2885 1854.54,2886.62 4139.01,2886.57 5143.1,2887.2 4277.45,2890.23 4108.33,2890.75 5185.66,2890.57 1766.91,2892.72 1889.83,2892.66 4308.13,2892.72 2581.43,2893.96 3896.43,2893.96 2926,2895 5109.26,2895.86 2892,2897 5307.66,2896.86 1729.06,2899.44 3140.24,2899.37 4212.28,2898.86 3002.55,2900.49 4181.6,2900.98 1822.46,2901.79 3033.41,2902.9 5216.34,2902.96 1918.84,2903.63 3170.59,2904.48 5338.34,2903.59 1852.71,2907.21 4139.01,2907.24 5137.78,2907.17 1757.84,2911.29 4108.33,2911.42 4277.45,2910.9 5185.66,2911.24 1884.76,2912.7 4308.13,2913.39 2923,2914 5098.94,2913.77 1715.75,2915.25 5307,2917.51 2581.43,2919.55 3136.39,2919.68 3896.43,2919.55 4212.28,2919.53 1815.89,2921.39 3000.55,2921.06 3031.23,2921.06 2888,2922 4181.6,2921.65 1913.5,2923.6 5215.7,2923.62 5337.14,2924.23 3166.66,2924.78 5128.3,2925.54 1699.08,2927.48 1846.67,2926.98 1411.43,2927.91 1745.79,2928.09 4139.01,2927.91 4899.43,2927.91 5083.57,2927.59 1877.92,2932.2 2919,2932 4108.33,2932.09 4277.45,2931.57 5183.07,2931.75 4308.13,2934.06 1679.94,2935.27 5064.67,2935.96 1393.72,2938.14 1429.15,2938.16 1449.82,2938.16 1470.49,2938.16 1494.11,2938.16 1514.78,2938.16 1535.45,2938.16 1556.12,2938.16 1576.79,2938.16 1597.46,2938.16 1618.13,2938.16 1638.8,2938.16 1659.47,2938.15 4881.72,2938.14 4917.15,2938.16 4937.82,2938.16 4958.49,2938.16 4982.11,2938.16 5002.78,2938.16 5023.45,2938.16 5044.12,2938.16 5303.61,2937.9 1806.4,2939.75 3000.55,2939.68 3134.66,2940.28 4212.28,2940.2 5115.12,2941.46 3031.23,2941.73 4181.6,2942.32 1731.08,2942.61 1906.6,2943.08 5211.5,2943.86 2880,2945 3165.24,2945.4 5333.55,2944.58 1838.22,2945.84 2914.01,2948 4139.01,2948.58 1869.35,2951.01 5175.15,2950.84 4277.45,2952.24 1385.84,2953.5 4108.33,2952.76 4873.84,2953.5 1714.02,2954.28 5098.86,2954.22 4308.13,2954.73 1794.22,2956.45 5297.4,2957.62 2873,2960 3000.55,2960.35 3134.55,2960.95 4212.28,2960.87 1898.18,2961.96 3031.23,2962.4 1695.14,2962.69 1827.48,2963.5 4181.6,2962.99 5080.25,2963.21 5203.53,2962.93 5327.64,2964.39 3165.23,2966.07 5162.47,2967.16 1675.06,2967.58 5060.15,2968.04 1393.72,2968.85 1429.15,2968.84 1449.82,2968.84 1470.49,2968.84 1489.06,2968.84 1509.73,2968.84 1530.4,2968.84 1551.07,2968.84 1571.74,2968.84 1592.41,2968.84 1613.08,2968.84 1633.75,2968.84 1654.42,2968.84 1859.14,2968.98 4139.01,2969.25 4881.72,2968.85 4917.15,2968.84 4937.82,2968.84 4958.49,2968.84 4977.49,2968.84 4998.16,2968.84 5018.83,2968.84 5039.5,2968.84 1779.47,2970.93 4108.33,2973.43 4277.45,2972.91 2901.61,2973.88 2865,2975 4308.13,2975.4 5288.49,2976.27 1411.43,2979.09 4899.43,2979.09 1814.63,2979.69 1888.3,2980.11 4181,2980 5145.92,2979.54 5192.08,2980.14 3000.55,2981.02 3031.23,2981.07 1761.81,2981.68 3134.55,2981.62 5319.46,2983.37 4212.28,2983.66 1847.36,2985.97 3165.23,2986.74 5126.68,2987.11 1742.1,2987.89 1393.72,2989.32 1429.15,2989.34 1449.82,2989.34 1470.49,2989.34 1494.11,2989.34 1514.78,2989.34 1535.45,2989.34 1556.12,2989.34 1576.79,2989.34 1597.46,2989.34 1618.13,2989.34 1638.8,2989.34 1659.47,2989.34 1680.14,2989.34 1700.81,2989.34 1721.48,2989.34 2855.9,2989.39 4881.72,2989.32 4917.15,2989.34 4937.82,2989.34 4958.49,2989.34 4982.11,2989.34 5002.78,2989.34 5023.45,2989.34 5044.12,2989.34 5064.79,2989.34 5085.46,2989.34 5106.13,2989.34 4138.32,2989.91 2891.44,2991.88 5277.06,2993.5 1799.73,2994.01 4106.3,2994 4277.45,2993.58 5177.56,2994.85 4308.13,2996.07 1877.01,2997.42 4180.72,2996.56 5309.14,3001.28 1834.1,3001.83 3000.55,3001.69 3031.23,3001.74 3133.97,3002.28 4210.59,3004.26 1385.84,3004.68 2842.52,3005.14 4873.84,3004.68 1782.58,3005.56 3164.3,3007.39 5160.51,3006.53 2879.64,3008.84 5263.33,3008.94 4133.29,3009.96 4097.11,3012.52 1763.66,3013.89 1864.38,3013.79 4277.45,3014.25 5141.54,3014.75 1819.29,3016.24 4175.74,3016.62 4308.13,3016.74 5296.82,3017.88 1743.57,3018.74 2826.9,3018.68 5121.36,3019.22 1393.72,3020.03 1429.15,3020.02 1449.82,3020.02 1470.49,3020.02 1495.57,3020.02 1516.24,3020.02 1536.91,3020.02 1557.58,3020.02 1578.25,3020.02 1598.92,3020.02 1619.59,3020.02 1640.26,3020.02 1660.93,3020.02 1681.6,3020.02 1702.27,3020.02 1722.94,3020.02 4881.72,3020.03 4917.15,3020.02 4937.82,3020.02 4958.49,3020.02 4976.69,3020.02 4997.36,3020.02 5018.03,3020.02 5038.7,3020.02 5059.37,3020.02 5080.04,3020.02 5100.71,3020.02 2581.43,3021.91 3000.55,3022.36 3031.23,3022.36 3896.43,3021.91 5247.24,3021.91 3130.49,3022.66 4205.55,3024.31 2866.29,3024.63 4081.6,3026.17 1802.12,3027.75 2808.38,3027.85 3160.82,3027.76 4123.61,3028.22 1850.5,3029.11 1411.43,3030.27 4899.43,3030.27 2563.72,3032.14 2599.15,3032.16 2619.82,3032.16 2640.49,3032.16 2664.1,3032.16 2684.77,3032.16 2705.44,3032.16 2726.11,3032.16 2746.78,3032.16 2767.45,3032.16 2788.12,3031.96 3878.72,3032.14 3914.15,3032.16 3934.82,3032.16 3955.49,3032.16 3979.1,3032.16 3999.77,3032.16 4020.44,3032.16 4041.11,3032.16 4061.78,3032.05 5229.03,3031.69 5282.64,3032.91 4166.55,3035.14 4277.45,3034.92 1783.06,3035.74 2855.01,3037 4308.13,3037.41 5209.33,3037.95 1762.81,3039.92 5188.81,3040.47 1393.72,3040.5 1429.15,3040.52 1449.82,3040.52 1470.49,3040.52 1494.11,3040.52 1514.78,3040.52 1535.45,3040.52 1556.12,3040.52 1576.79,3040.52 1597.46,3040.52 1618.13,3040.52 1638.8,3040.52 1659.47,3040.52 1680.14,3040.52 1700.81,3040.52 1721.48,3040.52 1742.15,3040.52 4881.72,3040.5 4917.15,3040.52 4937.82,3040.52 4958.49,3040.52 4982.11,3040.52 5002.78,3040.52 5023.45,3040.52 5044.12,3040.52 5064.79,3040.52 5085.46,3040.52 5106.13,3040.52 5126.8,3040.52 5147.47,3040.52 5168.14,3040.52 3123.94,3042.26 1835.08,3042.86 3029.21,3043 4197.32,3043.27 4109.84,3043.63 2555.84,3047.5 3870.84,3047.5 2993,3048 3154.84,3047.55 2833.96,3050.12 5263,3050 4151.28,3053.5 1817.77,3054.16 4092.58,3055.02 1385.84,3055.86 4275.78,3055.53 4873.84,3055.86 2814.85,3057.99 4306.55,3058.02 5247,3058 3027,3060 3114.47,3060.63 4072.95,3061.49 4186.1,3060.63 2794.61,3062.17 1798.96,3062.74 2563.72,3062.85 2599.15,3062.84 2619.82,3062.84 2640.49,3062.84 2670.6,3062.84 2691.27,3062.83 2711.94,3062.83 2732.61,3062.83 2753.28,3062.83 2777.95,3062.83 3878.72,3062.85 3914.15,3062.84 3934.82,3062.84 3955.49,3062.84 3973,3063 3990.32,3062.84 4010.99,3062.84 4031.66,3062.84 4052.33,3062.84 5229.6,3064.2 3146.44,3066.43 4134.97,3066.2 2982,3067 1779.08,3068.4 5209.54,3069.16 1393.72,3071.21 1429.15,3071.2 1449.82,3071.2 1470.49,3071.2 1489.87,3071.2 1510.54,3071.2 1531.21,3071.2 1551.88,3071.2 1572.55,3071.2 1593.22,3071.2 1613.89,3071.2 1634.56,3071.2 1655.23,3071.2 1675.9,3071.2 1696.57,3071.2 1717.24,3071.2 1737.91,3071.2 1758.58,3071.02 4881.72,3071.21 4917.15,3071.2 4937.82,3071.2 4958.49,3071.2 4982.26,3071.2 5002.93,3071.2 5023.6,3071.2 5044.27,3071.2 5064.94,3071.2 5085.61,3071.2 5106.28,3071.2 5126.95,3071.2 5147.62,3071.2 5168.29,3071.2 2581.43,3073.09 3896.43,3073.09 4175.29,3072.94 5189,3073 4268.59,3074.9 4116.56,3075.61 3102.31,3077.34 4300.96,3077.92 2969.39,3078.53 1155.53,3081.45 1206.71,3081.45 1257.89,3081.45 1309.07,3081.45 1411.43,3081.45 3013,3081 4096.72,3081.39 4643.53,3081.45 4694.71,3081.45 4745.89,3081.45 4797.07,3081.45 4899.43,3081.45 4079,3082 2563.72,3083.32 2599.15,3083.34 2619.82,3083.34 2640.49,3083.34 2664.11,3083.34 2684.78,3083.34 2705.45,3083.34 2726.12,3083.34 2746.79,3083.34 2769.46,3083.34 2788.13,3083.34 2808.8,3083.34 2829.47,3083.34 2848.14,3083.34 2866.81,3083.34 2885.48,3083.34 2912.15,3083.34 2932.82,3083.34 2949.29,3083.34 3878.72,3083.32 3914.15,3083.34 3934.82,3083.34 3955.49,3083.34 3979.11,3083.34 3999.78,3083.34 4020.45,3083.34 4041.12,3083.34 4061.79,3083.34 3135.75,3084.12 4159.64,3086.44 1140.18,3089.33 1170.89,3089.33 1191.36,3089.33 1222.07,3089.33 1242.54,3089.33 1273.25,3089.33 1293.72,3089.33 1324.43,3089.33 4628.18,3089.33 4658.89,3089.33 4679.36,3089.33 4710.07,3089.33 4730.54,3089.33 4761.25,3089.33 4781.72,3089.33 4812.43,3089.33 3089,3090 4256.26,3091.5 3001.01,3094 4291.54,3096.31 4142.17,3097.49 3126,3098 2555.84,3098.68 3870.84,3098.68 3075,3102 2985.87,3104.49 4123.27,3105.86 4241.2,3105.65 1129.94,3107.04 1181.12,3107.04 1232.3,3107.04 1283.48,3107.04 1334.66,3107.04 4617.94,3107.04 4669.11,3107.04 4720.29,3107.04 4771.47,3107.04 3114,3110 4103.34,3111.35 2966.61,3111.99 4278.66,3112.48 2563.72,3114.03 2599.15,3114.02 2619.82,3114.02 2640.49,3114.02 2659.92,3114.02 2680.59,3114.02 2701.26,3114.02 2721.93,3114.02 2742.6,3114.02 2763.27,3114.02 2783.94,3114.02 2804.61,3114.02 2825.28,3114.02 2845.95,3114.02 2866.62,3114.02 2887.29,3114.02 2913.96,3114.02 2932.63,3114.02 2949.3,3114.02 3055,3114 3878.72,3114.03 3914.15,3114.02 3934.82,3114.02 3955.49,3114.02 3972.79,3114.02 3993.46,3114.02 4014.13,3114.02 4034.8,3114.02 4055.47,3114.02 4076.14,3114.02 4224.19,3117.4 3101,3121 2581.43,3124.27 3034.92,3123.87 3896.43,3124.27 1140.19,3124.76 1170.87,3124.76 1191.37,3124.76 1222.05,3124.76 1242.55,3124.76 1273.23,3124.76 1293.73,3124.76 1324.41,3124.76 4628.19,3124.76 4658.87,3124.76 4679.37,3124.76 4710.05,3124.76 4730.55,3124.76 4761.23,3124.76 4781.73,3124.76 4812.41,3124.76 4205.51,3126.25 4263.74,3126.79 3015.15,3129.9 4185.65,3131.98 2994.79,3133.47 3084,3134 4165.13,3134.43 2563.72,3134.5 2599.15,3134.52 2619.82,3134.52 2640.49,3134.52 2664.1,3134.52 2684.77,3134.52 2705.44,3134.52 2726.11,3134.52 2744.78,3134.52 2767.45,3134.52 2788.12,3134.52 2808.79,3134.52 2829.46,3134.52 2850.13,3134.52 2870.8,3134.52 2891.47,3134.52 2914.14,3134.52 2932.81,3134.52 2953.48,3134.52 2974.15,3134.52 3878.72,3134.5 3914.15,3134.52 3934.82,3134.52 3955.49,3134.52 3979.1,3134.52 3999.77,3134.52 4020.44,3134.52 4041.11,3134.52 4061.78,3134.52 4082.45,3134.52 4103.12,3134.52 4123.79,3134.52 4144.46,3134.52 4247.23,3139.23 3069,3142 1140.19,3145.43 1170.87,3145.43 1191.37,3145.43 1222.05,3145.43 1242.55,3145.43 1273.23,3145.43 1293.73,3145.43 1324.41,3145.43 4628.19,3145.43 4658.87,3145.43 4679.37,3145.43 4710.05,3145.43 4730.55,3145.43 4761.23,3145.43 4781.73,3145.43 4812.41,3145.43 4229.25,3149.41 1344.91,3150.35 1375.59,3150.35 1396.09,3150.35 1426.77,3150.35 2555.84,3149.86 3053,3150 3870.84,3149.86 4884.09,3150.35 4914.77,3150.35 3035,3156 4210.09,3157.17 3016.97,3160.94 4190.08,3162.37 2563.72,3165.21 2599.15,3165.2 2619.82,3165.2 2640.49,3165.2 2665.96,3165.2 2686.63,3165.2 2707.3,3165.2 2725.97,3165.2 2744.64,3165.2 2769.31,3165.2 2789.98,3165.2 2810.65,3165.2 2831.32,3165.2 2851.99,3165.2 2872.66,3165.2 2893.33,3165.2 2916,3165.2 2934.67,3165.2 2955.34,3165.2 2976.01,3165.2 2998,3165 3878.72,3165.21 3914.15,3165.2 3934.82,3165.2 3955.49,3165.2 3979,3165 4002,3165 4024.88,3165.2 4045.55,3165.2 4066.22,3165.2 4086.89,3165.2 4107.56,3165.2 4128.23,3165.2 4148.9,3165.2 4169.57,3164.93 1140.19,3166.1 1170.87,3166.1 1191.37,3166.1 1222.05,3166.1 1242.55,3166.1 1273.23,3166.1 1293.73,3166.1 1324.41,3166.1 4628.19,3166.1 4658.87,3166.1 4679.37,3166.1 4710.05,3166.1 4730.55,3166.1 4761.23,3166.1 4781.73,3166.1 4812.41,3166.1 1344.91,3171.02 1375.59,3171.02 1396.09,3171.02 1426.77,3171.02 4916,3174 2325.53,3175.45 2376.71,3175.45 2427.89,3175.45 2479.07,3175.45 2581.43,3175.45 3640.53,3175.45 3691.71,3175.45 3742.89,3175.45 3794.07,3175.45 3896.43,3175.45 4883,3177 2310.18,3183.33 2340.89,3183.33 2361.36,3183.33 2392.07,3183.33 2412.54,3183.33 2443.25,3183.33 2463.72,3183.33 2494.43,3183.33 3625.18,3183.33 3655.89,3183.33 3676.36,3183.33 3707.07,3183.33 3727.54,3183.33 3758.25,3183.33 3778.72,3183.33 3809.43,3183.33 4679.36,3183.2 4730.55,3183.2 4781.73,3183.2 1242.55,3184.39 4628.19,3184.15 4658.87,3184.72 4812.41,3184.72 1140,3186 4710.04,3185.72 4761.23,3185.72 1170.87,3189.72 1222.05,3189.72 1273.23,3189.72 1324.41,3189.72 1344.91,3191.69 1377,3192 1396.09,3191.69 1426.77,3191.69 1191.37,3193.98 1293.73,3194.34 4953.43,3197.57 4892,3199 4679.36,3200.3 2299.94,3201.04 2351.12,3201.04 2402.3,3201.04 2453.48,3201.04 2504.66,3201.04 3614.94,3201.04 3666.11,3201.04 3717.29,3201.04 3768.47,3201.04 4730.55,3200.83 4781.73,3201.1 4710.04,3202.39 4628.19,3202.82 4658.85,3203.39 4761.23,3204.39 1140.19,3204.93 1242.55,3205.06 4812.41,3205.39 1170.87,3210.39 1222.05,3210.39 1273.23,3210.39 1324.41,3210.39 1344.91,3212.36 1191.37,3214.65 1293.73,3215.01 2310.19,3218.76 2340.87,3218.76 2361.37,3218.76 2392.05,3218.76 2412.55,3218.76 2443.23,3218.76 2463.73,3218.76 2494.41,3218.76 3625.19,3218.76 3655.87,3218.76 3676.37,3218.76 3707.05,3218.76 3727.55,3218.76 3758.23,3218.76 3778.73,3218.76 3809.41,3218.76 4626.1,3225.38 4679,3225 4710,3225 4730.55,3225.5 4762,3225 1139.37,3225.58 1242.55,3225.73 4658,3226 4781.73,3225.77 1169.58,3231.02 1222.05,3231.06 1273.23,3231.06 1324.41,3231.06 4812.46,3231.06 1191.37,3235.32 1293.73,3235.68 1382.54,3236 1440.32,3236 4912.57,3238.43 4953.42,3238.42 2310.19,3239.43 2340.87,3239.43 2361.37,3239.43 2392.05,3239.43 2412.55,3239.43 2443.23,3239.43 2463.73,3239.43 2494.41,3239.43 3625.19,3239.43 3655.87,3239.43 3676.37,3239.43 3707.05,3239.43 3727.55,3239.43 3758.23,3239.43 3778.73,3239.43 3809.41,3239.43 1364,3241 4730.55,3242.17 4782.73,3242.41 4676,3243 2514.91,3244.35 2545.59,3244.35 2566.09,3244.35 2596.77,3244.35 3829.91,3244.35 3860.59,3244.35 3881.19,3244.35 3911.67,3244.35 4617.81,3244.32 1133.92,3245.52 1242.55,3246.4 4708,3247 4762,3247 4651,3248 1164.61,3251.08 4816.47,3251.34 1221.32,3251.72 1273.23,3251.73 1324.41,3251.73 1189.83,3255.93 1293.73,3256.35 2310.19,3260.1 2340.87,3260.1 2361.37,3260.1 2392.05,3260.1 2412.55,3260.1 2443.23,3260.1 2463.73,3260.1 2494.41,3260.1 3625.19,3260.1 3655.87,3260.1 3676.37,3260.1 3707.05,3260.1 3727.55,3260.1 3758.23,3260.1 3778.73,3260.1 3809.41,3260.1 4604.05,3259.74 4668.77,3260.41 4787.86,3262.44 1123.67,3263.47 4730.55,3262.84 1411.43,3264.88 2514.91,3265.02 2545.59,3265.02 2566.09,3265.02 2598.77,3265.02 3829.91,3265.02 3860.59,3265.02 3881.19,3265.02 3911.67,3265.02 1242.55,3267.07 4638.6,3267.99 4826.55,3269.38 1156.07,3269.91 1273.23,3270 4586.33,3270.39 4698.39,3270.54 1217.82,3272.09 1324.41,3272.4 4761.23,3272.4 4566.28,3275.39 1184.7,3275.96 4338.91,3275.96 4359.58,3275.72 4380.25,3275.72 4400.92,3275.72 4421.59,3275.72 4442.26,3275.72 4462.93,3275.72 4483.6,3275.72 4504.27,3275.72 4524.94,3275.72 4545.61,3275.72 4655.22,3276.03 1293.73,3277.02 2310,3277 2361,3277 2463,3277 3625,3278 3778,3278.45 1109.65,3278.65 3675.45,3278.9 3726.25,3278.55 4318.96,3281.35 4797.14,3280.91 2644,3282.11 4624.24,3282.85 4842.01,3283.1 2340.87,3283.72 2392.04,3283.72 2443.23,3283.72 2494.41,3283.72 3655.87,3283.72 3707.04,3283.72 3758.23,3283.72 3809.41,3283.72 4730.55,3283.51 2602,3285 2412.55,3285.61 2514.91,3285.69 2546.58,3285.99 3829.91,3285.69 3860.59,3285.69 1144.24,3286.86 1242.55,3287.74 1273.22,3287.73 3881.09,3288.27 3911.77,3288.27 4686.67,3287.57 4861.68,3289.46 4882.35,3289.72 4903.02,3289.72 4923.69,3289.72 4944.36,3289.72 4965.03,3289.72 4985.7,3289.72 5006.37,3289.72 5027.04,3289.72 5047.71,3289.72 5068.38,3289.72 5089.05,3289.72 5109.72,3289.72 5130.39,3289.72 5151.06,3289.72 5171.73,3289.72 5192.4,3289.72 5213.07,3289.72 5237,3290 4640.61,3290.64 1211.52,3291.77 2568.86,3292.37 5255,3292 1095.03,3293.27 1324.44,3293.07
